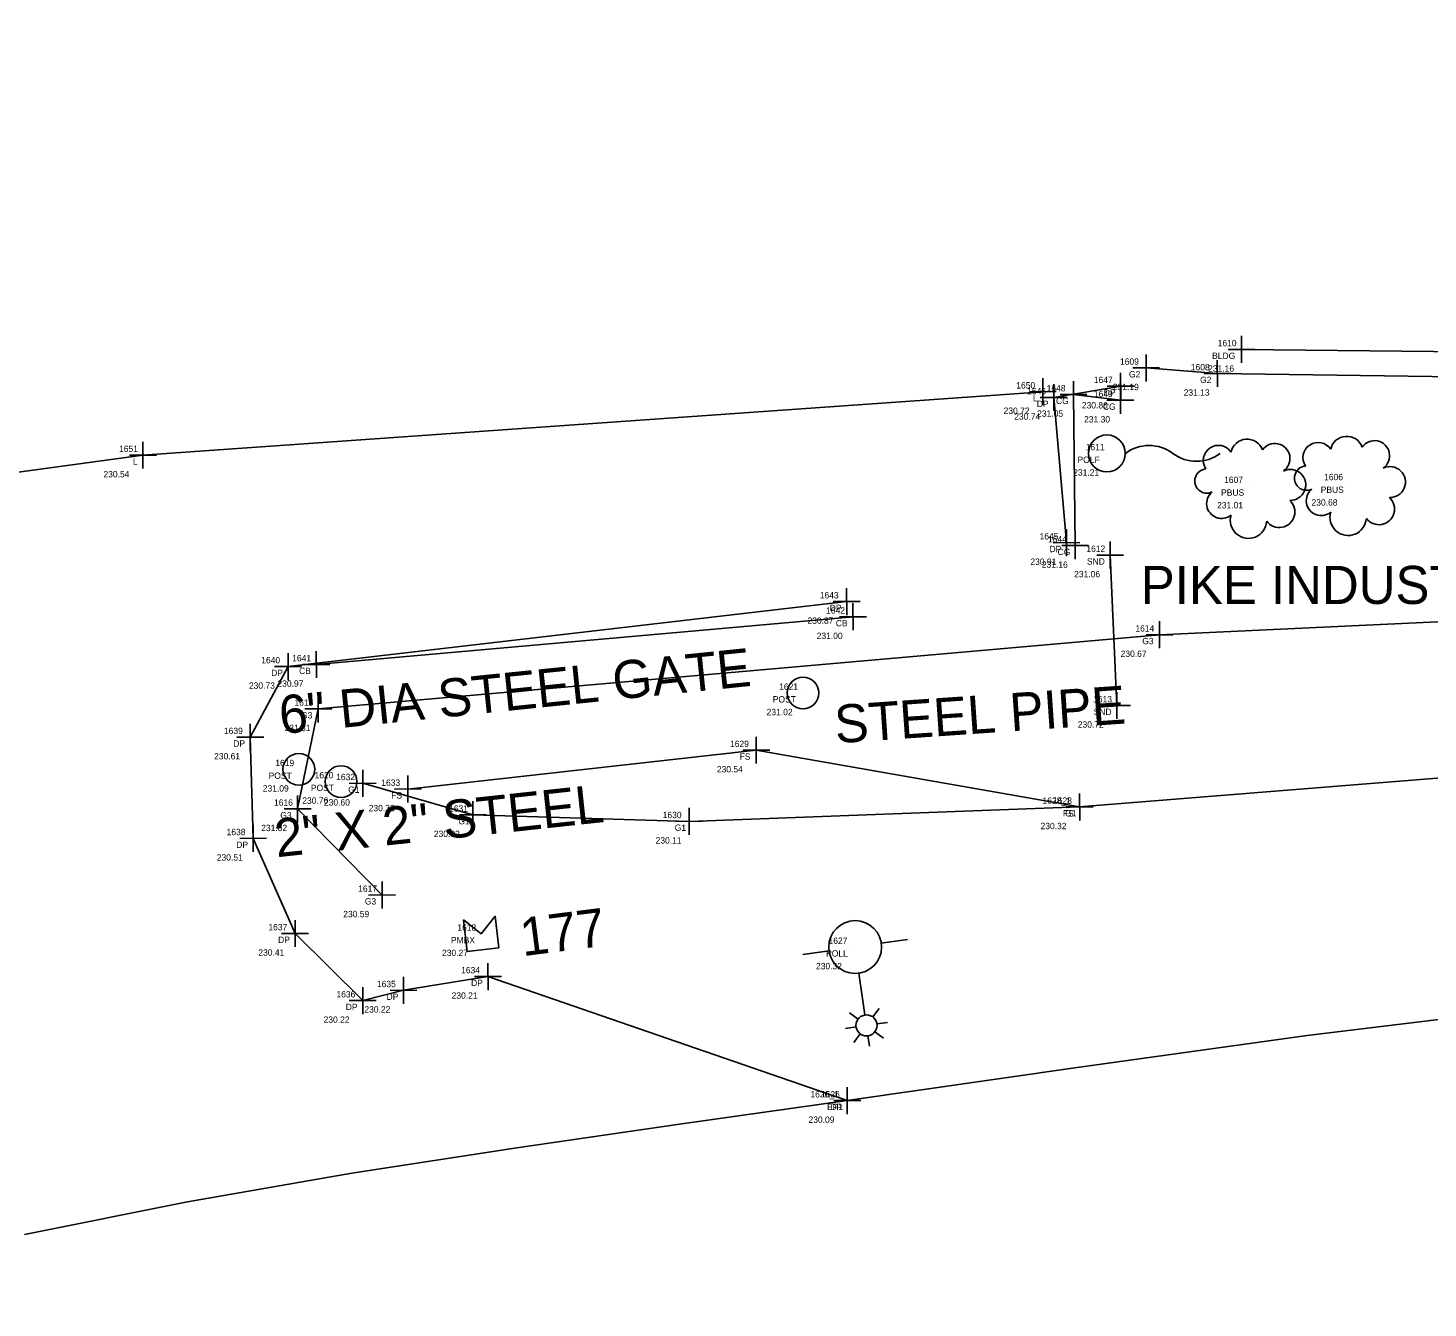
# Model space of a CAD drawing. Extents: x 1155460 to 1157069, y 590691 to 591363.
# Drawn here: x 1155557.4 to 1155623.6, y 591219.6 to 591280.1 of the extents above; entities that cross this region are included whole.
import ezdxf

# ---------------------------------------------------------------- set-up
doc = ezdxf.new("R2010")
doc.units = 0
for name, color, linetype in [('Default', 7, 'Continuous'), ('S_Buildings', 7, 'Continuous'), ('S_Curb_Type_1', 7, 'Continuous'), ('S_Curb_Type_3', 7, 'Continuous'), ('S_Fencing_StockadePostPlank', 7, 'Continuous'), ('S_Field_Code', 7, 'Continuous'), ('S_Ground_Elevation', 7, 'Continuous'), ('S_Ground_LevelString', 7, 'Continuous'), ('S_Point_Elevation', 7, 'Continuous'), ('S_Point_Name', 7, 'Continuous'), ('S_Property_FlagPole', 7, 'Continuous'), ('S_Property_Mailbox', 7, 'Continuous'), ('S_Roadway_Drive_Paved', 7, 'Continuous'), ('S_Roadway_Edge_Pavement', 7, 'Continuous'), ('S_Survey_Shot', 7, 'Continuous'), ('S_Text', 7, 'Continuous'), ('S_Traffic_Posts', 7, 'Continuous'), ('S_Traffic_Sign_DoublePost', 7, 'Continuous'), ('S_Trees_Bush', 7, 'Continuous'), ('S_Utilities_Pole_StreetLight', 7, 'Continuous')]:
    doc.layers.add(name, color=color, linetype=linetype)

msp = doc.modelspace()

# ---------------------------------------------------------------- linework, layer by layer
at = {"layer": 'Default'}
for p, q in [((1155608.443, 591260.021), (1155608.443, 591260.021)), ((1155615.243, 591258.471), (1155615.243, 591258.471)), ((1155619.953, 591258.605), (1155619.953, 591258.605)), ((1155594.081, 591248.698), (1155594.081, 591248.698)), ((1155570.251, 591245.089), (1155570.251, 591245.089)), ((1155572.25, 591244.511), (1155572.25, 591244.511)), ((1155578.87, 591237.315), (1155578.87, 591237.315)), ((1155596.546, 591236.689), (1155596.546, 591236.689))]:
    msp.add_line(p, q, dxfattribs=at)
at = {"layer": 'S_Buildings'}
msp.add_lwpolyline([(1155665.229, 591280.129), (1155664.719, 591264.411), (1155614.806, 591264.937)], dxfattribs=at)
at = {"layer": 'S_Curb_Type_1'}
msp.add_lwpolyline([(1155606.945, 591255.665), (1155606.868, 591262.804), (1155609.086, 591262.533)], dxfattribs=at)
at = {"layer": 'S_Curb_Type_3'}
msp.add_lwpolyline([(1155596.445, 591252.301), (1155571.078, 591250.044)], dxfattribs=at)
at = {"layer": 'S_Fencing_StockadePostPlank'}
msp.add_lwpolyline([(1155575.404, 591244.158), (1155591.874, 591245.993), (1155607.156, 591243.31), (1155631.135, 591245.232), (1155662.71, 591249.078), (1155669.531, 591244.336)], dxfattribs=at)
at = {"layer": 'S_Ground_Elevation'}
for points in [[(1155713.472, 591273.726), (1155710.261, 591263.992), (1155677.396, 591264.939), (1155666.254, 591263.241), (1155644.102, 591263.369), (1155613.665, 591263.8), (1155610.303, 591264.062)], [(1155725.001, 591267.74), (1155722.525, 591258.653), (1155705.308, 591255.632), (1155675.425, 591255.158), (1155658.095, 591253.652), (1155610.931, 591251.452), (1155571.17, 591247.944), (1155570.19, 591243.218), (1155574.185, 591239.149)], [(1156064.685, 591169.992), (1156062.279, 591173.686), (1156058.171, 591175.677), (1156048.24, 591175.877), (1156021.632, 591181.666), (1156002.311, 591185.523), (1155967.868, 591192.884), (1155923.002, 591202.115), (1155873.133, 591212.797), (1155827.029, 591221.651), (1155786.006, 591228.636), (1155747.292, 591234.475), (1155721.081, 591237.232), (1155707.607, 591238.37), (1155671.241, 591246.232), (1155669.531, 591244.336), (1155631.135, 591245.232), (1155607.156, 591243.31), (1155588.703, 591242.631), (1155578.48, 591242.94), (1155573.27, 591244.428)]]:
    msp.add_lwpolyline(points, dxfattribs=at)
at = {"layer": 'S_Ground_LevelString'}
msp.add_lwpolyline([(1155605.415, 591262.939), (1155562.88, 591259.939), (1155527.197, 591255.067), (1155526.793, 591255.817)], dxfattribs=at)
at = {"layer": 'S_Property_FlagPole'}
msp.add_circle((1155608.443, 591260.021), 0.873, dxfattribs=at)
for centre, start, end in [((1155610.439, 591258.524), 53.1301, 126.8699), ((1155612.684, 591261.518), 233.1301, 306.8699)]:
    msp.add_arc(centre, 1.871, start, end, dxfattribs=at)
at = {"layer": 'S_Property_Mailbox'}
msp.add_lwpolyline([(1155578.04, 591237.971), (1155578.214, 591236.484), (1155579.701, 591236.658), (1155579.527, 591238.145), (1155578.87, 591237.315)], close=True, dxfattribs=at)
at = {"layer": 'S_Roadway_Drive_Paved'}
for points in [[(1155606.534, 591255.803), (1155605.93, 591262.665), (1155609.097, 591263.196)], [(1155596.173, 591229.43), (1155579.192, 591235.294), (1155575.198, 591234.643), (1155573.271, 591234.157), (1155570.071, 591237.331), (1155568.093, 591241.827), (1155567.952, 591246.609), (1155569.744, 591249.947), (1155596.144, 591253.017)]]:
    msp.add_lwpolyline(points, dxfattribs=at)
at = {"layer": 'S_Roadway_Edge_Pavement'}
msp.add_lwpolyline([(1155628.79, 591233.837), (1155617.91, 591232.509), (1155607.044, 591230.997), (1155596.173, 591229.43), (1155588.36, 591228.326), (1155580.548, 591227.201), (1155572.755, 591225.996), (1155564.994, 591224.651), (1155557.283, 591223.108)], dxfattribs=at)
at = {"layer": 'S_Survey_Shot'}
for p, q in [((1155614.807, 591264.301), (1155614.805, 591265.574)), ((1155610.304, 591263.426), (1155610.302, 591264.699)), ((1155614.17, 591264.936), (1155615.442, 591264.939)), ((1155614.806, 591264.937), (1155614.806, 591264.937)), ((1155609.667, 591264.061), (1155610.939, 591264.064)), ((1155610.303, 591264.062), (1155610.303, 591264.062)), ((1155613.666, 591263.164), (1155613.663, 591264.436)), ((1155605.417, 591262.303), (1155605.414, 591263.576)), ((1155606.87, 591262.168), (1155606.867, 591263.441)), ((1155609.098, 591262.559), (1155609.095, 591263.832)), ((1155613.028, 591263.798), (1155614.301, 591263.801)), ((1155613.665, 591263.8), (1155613.665, 591263.8)), ((1155604.779, 591262.938), (1155606.051, 591262.941)), ((1155605.415, 591262.939), (1155605.415, 591262.939)), ((1155605.932, 591262.029), (1155605.929, 591263.301)), ((1155606.232, 591262.803), (1155607.504, 591262.806)), ((1155606.868, 591262.804), (1155606.868, 591262.804)), ((1155608.46, 591263.194), (1155609.733, 591263.197)), ((1155609.087, 591261.897), (1155609.084, 591263.169)), ((1155609.097, 591263.196), (1155609.097, 591263.196)), ((1155605.294, 591262.664), (1155606.567, 591262.667)), ((1155605.93, 591262.665), (1155605.93, 591262.665)), ((1155608.449, 591262.532), (1155609.722, 591262.534)), ((1155609.086, 591262.533), (1155609.086, 591262.533)), ((1155562.881, 591259.302), (1155562.878, 591260.575)), ((1155562.243, 591259.937), (1155563.516, 591259.94)), ((1155562.88, 591259.939), (1155562.88, 591259.939)), ((1155606.535, 591255.167), (1155606.533, 591256.439)), ((1155606.946, 591255.029), (1155606.944, 591256.301)), ((1155605.898, 591255.802), (1155607.17, 591255.804)), ((1155606.309, 591255.664), (1155607.581, 591255.666)), ((1155606.534, 591255.803), (1155606.534, 591255.803)), ((1155606.945, 591255.665), (1155606.945, 591255.665)), ((1155608.602, 591254.58), (1155608.599, 591255.853)), ((1155607.964, 591255.215), (1155609.237, 591255.218)), ((1155608.601, 591255.217), (1155608.601, 591255.217)), ((1155596.145, 591252.381), (1155596.143, 591253.653)), ((1155595.508, 591253.016), (1155596.78, 591253.018)), ((1155596.144, 591253.017), (1155596.144, 591253.017)), ((1155596.446, 591251.664), (1155596.443, 591252.937)), ((1155595.808, 591252.299), (1155597.081, 591252.302)), ((1155596.445, 591252.301), (1155596.445, 591252.301)), ((1155610.295, 591251.451), (1155611.568, 591251.453)), ((1155610.933, 591250.816), (1155610.93, 591252.088)), ((1155610.931, 591251.452), (1155610.931, 591251.452)), ((1155569.745, 591249.31), (1155569.742, 591250.583)), ((1155571.079, 591249.408), (1155571.076, 591250.68)), ((1155569.107, 591249.945), (1155570.38, 591249.948)), ((1155569.744, 591249.947), (1155569.744, 591249.947)), ((1155570.441, 591250.043), (1155571.714, 591250.045)), ((1155571.078, 591250.044), (1155571.078, 591250.044)), ((1155571.171, 591247.307), (1155571.168, 591248.58)), ((1155608.922, 591247.47), (1155608.919, 591248.742)), ((1155570.534, 591247.942), (1155571.806, 591247.945)), ((1155571.17, 591247.944), (1155571.17, 591247.944)), ((1155608.284, 591248.105), (1155609.557, 591248.107)), ((1155608.921, 591248.106), (1155608.921, 591248.106)), ((1155567.954, 591245.973), (1155567.951, 591247.245)), ((1155567.316, 591246.608), (1155568.589, 591246.61)), ((1155567.952, 591246.609), (1155567.952, 591246.609)), ((1155591.875, 591245.357), (1155591.873, 591246.629)), ((1155591.238, 591245.992), (1155592.51, 591245.994)), ((1155591.874, 591245.993), (1155591.874, 591245.993)), ((1155573.272, 591243.791), (1155573.269, 591245.064)), ((1155572.634, 591244.426), (1155573.907, 591244.429)), ((1155573.27, 591244.428), (1155573.27, 591244.428)), ((1155575.405, 591243.522), (1155575.402, 591244.794)), ((1155570.192, 591242.581), (1155570.189, 591243.854)), ((1155574.767, 591244.157), (1155576.04, 591244.16)), ((1155575.404, 591244.158), (1155575.404, 591244.158)), ((1155578.482, 591242.304), (1155578.479, 591243.577)), ((1155607.158, 591242.674), (1155607.155, 591243.946)), ((1155607.158, 591242.674), (1155607.155, 591243.946)), ((1155569.554, 591243.216), (1155570.826, 591243.219)), ((1155570.19, 591243.218), (1155570.19, 591243.218)), ((1155577.844, 591242.939), (1155579.117, 591242.942)), ((1155578.48, 591242.94), (1155578.48, 591242.94)), ((1155588.705, 591241.995), (1155588.702, 591243.268)), ((1155606.52, 591243.309), (1155607.793, 591243.311)), ((1155606.52, 591243.309), (1155607.793, 591243.311)), ((1155607.156, 591243.31), (1155607.156, 591243.31)), ((1155607.156, 591243.31), (1155607.156, 591243.31)), ((1155568.095, 591241.191), (1155568.092, 591242.464)), ((1155588.067, 591242.63), (1155589.339, 591242.633)), ((1155588.703, 591242.631), (1155588.703, 591242.631)), ((1155567.457, 591241.826), (1155568.73, 591241.829)), ((1155568.093, 591241.827), (1155568.093, 591241.827)), ((1155574.187, 591238.512), (1155574.184, 591239.785)), ((1155573.549, 591239.147), (1155574.821, 591239.15)), ((1155574.185, 591239.149), (1155574.185, 591239.149)), ((1155570.072, 591236.694), (1155570.07, 591237.967)), ((1155569.435, 591237.329), (1155570.707, 591237.332)), ((1155570.071, 591237.331), (1155570.071, 591237.331)), ((1155579.194, 591234.658), (1155579.191, 591235.93)), ((1155575.199, 591234.007), (1155575.197, 591235.279)), ((1155578.556, 591235.292), (1155579.829, 591235.295)), ((1155579.192, 591235.294), (1155579.192, 591235.294)), ((1155573.272, 591233.52), (1155573.27, 591234.793)), ((1155574.562, 591234.642), (1155575.834, 591234.644)), ((1155575.198, 591234.643), (1155575.198, 591234.643)), ((1155572.635, 591234.155), (1155573.907, 591234.158)), ((1155573.271, 591234.157), (1155573.271, 591234.157)), ((1155596.174, 591228.794), (1155596.171, 591230.067)), ((1155596.174, 591228.794), (1155596.171, 591230.067)), ((1155595.536, 591229.429), (1155596.809, 591229.432)), ((1155595.536, 591229.429), (1155596.809, 591229.432)), ((1155596.173, 591229.43), (1155596.173, 591229.43)), ((1155596.173, 591229.43), (1155596.173, 591229.43))]:
    msp.add_line(p, q, dxfattribs=at)
at = {"layer": 'S_Traffic_Posts'}
for centre in [(1155594.081, 591248.698), (1155570.251, 591245.089), (1155572.25, 591244.511)]:
    msp.add_circle(centre, 0.749, dxfattribs=at)
at = {"layer": 'S_Traffic_Sign_DoublePost'}
msp.add_lwpolyline([(1155608.601, 591255.217), (1155608.921, 591248.106)], dxfattribs=at)
at = {"layer": 'S_Trees_Bush'}
for centre, radius, start, end in [((1155619.78, 591260.056), 0.774, 19.72769, 168.00323), ((1155613.717, 591259.687), 0.716, 33.64054, 213.59091), ((1155615.07, 591259.922), 0.774, 19.72769, 168.00323), ((1155616.385, 591259.777), 0.714, 304.7168, 145.28321), ((1155618.427, 591259.821), 0.716, 33.64054, 213.59091), ((1155621.095, 591259.911), 0.714, 304.7168, 145.28321), ((1155617.883, 591258.853), 0.575, 95.18751, 295.46148), ((1155621.823, 591258.667), 0.731, 268.12197, 116.01721), ((1155613.173, 591258.718), 0.575, 95.18751, 295.46148), ((1155617.112, 591258.533), 0.731, 268.12197, 116.01721), ((1155613.865, 591257.653), 0.705, 129.15555, 309.41051), ((1155618.575, 591257.787), 0.705, 129.15555, 309.41051), ((1155616.588, 591257.257), 0.74, 216.98087, 47.49649), ((1155621.299, 591257.391), 0.74, 216.98087, 47.49649), ((1155615.138, 591256.867), 0.861, 163.74266, 356.27601), ((1155619.849, 591257.001), 0.861, 163.74266, 356.27601)]:
    msp.add_arc(centre, radius, start, end, dxfattribs=at)
at = {"layer": 'S_Utilities_Pole_StreetLight'}
for p, q in [((1155597.78, 591236.867), (1155599.015, 591237.046)), ((1155595.311, 591236.51), (1155594.076, 591236.331)), ((1155596.724, 591235.454), (1155597.01, 591233.479)), ((1155597.381, 591233.384), (1155597.679, 591233.784)), ((1155596.682, 591233.283), (1155596.282, 591233.582)), ((1155597.576, 591233.056), (1155598.07, 591233.128)), ((1155596.588, 591232.913), (1155596.094, 591232.842)), ((1155596.783, 591232.585), (1155596.485, 591232.185)), ((1155597.153, 591232.491), (1155597.225, 591231.997)), ((1155597.482, 591232.686), (1155597.881, 591232.387))]:
    msp.add_line(p, q, dxfattribs=at)
for centre, radius in [((1155596.546, 591236.689), 1.248), ((1155597.082, 591232.985), 0.499)]:
    msp.add_circle(centre, radius, dxfattribs=at)

# ---------------------------------------------------------------- texts
at = {"layer": 'S_Field_Code'}
for s, p in [('BLDG', (1155613.419, 591264.487)), ('G2', (1155609.488, 591263.612)), ('G2', (1155612.85, 591263.35)), ('L', (1155604.943, 591262.489)), ('DP', (1155608.296, 591262.746)), ('DP', (1155605.13, 591262.215)), ('CG', (1155606.039, 591262.354)), ('CG', (1155608.256, 591262.083)), ('L', (1155562.407, 591259.489)), ('POLF', (1155607.056, 591259.571)), ('PBUS', (1155613.842, 591258.021)), ('PBUS', (1155618.552, 591258.155)), ('DP', (1155605.733, 591255.353)), ('CG', (1155606.116, 591255.215)), ('SND', (1155607.5, 591254.767)), ('DP', (1155595.343, 591252.567)), ('CB', (1155595.63, 591251.851)), ('G3', (1155610.116, 591251.002)), ('DP', (1155568.943, 591249.497)), ('CB', (1155570.263, 591249.594)), ('POST', (1155592.652, 591248.248)), ('G3', (1155570.355, 591247.494)), ('SND', (1155607.82, 591247.656)), ('DP', (1155567.152, 591246.159)), ('FS', (1155591.088, 591245.543)), ('POST', (1155568.822, 591244.639)), ('POST', (1155570.821, 591244.061)), ('G1', (1155572.585, 591243.978)), ('FS', (1155574.617, 591243.708)), ('G3', (1155569.375, 591242.768)), ('FS', (1155606.37, 591242.86)), ('G1', (1155606.472, 591242.86)), ('G1', (1155577.795, 591242.49)), ('G1', (1155588.018, 591242.181)), ('DP', (1155567.293, 591241.377)), ('G3', (1155573.37, 591238.699)), ('DP', (1155569.27, 591236.881)), ('PMBX', (1155577.441, 591236.865)), ('POLL', (1155595.173, 591236.239)), ('DP', (1155578.392, 591234.844)), ('DP', (1155574.397, 591234.193)), ('DP', (1155572.47, 591233.707)), ('EP1', (1155595.216, 591228.98)), ('DP', (1155595.372, 591228.98))]:
    msp.add_text(s, height=0.3, dxfattribs=at).set_placement(p)
at = {"layer": 'S_Point_Elevation'}
for s, p in [('231.16', (1155613.228, 591263.887)), ('231.19', (1155608.725, 591263.012)), ('231.13', (1155612.073, 591262.75)), ('230.72', (1155603.563, 591261.889)), ('231.05', (1155605.149, 591261.754)), ('230.86', (1155607.261, 591262.146)), ('230.74', (1155604.065, 591261.615)), ('231.30', (1155607.366, 591261.483)), ('230.54', (1155561.016, 591258.889)), ('231.21', (1155606.851, 591258.971)), ('231.01', (1155613.653, 591257.421)), ('230.68', (1155618.117, 591257.555)), ('230.91', (1155604.829, 591254.753)), ('231.16', (1155605.367, 591254.615)), ('231.06', (1155606.895, 591254.167)), ('230.87', (1155594.292, 591251.967)), ('231.00', (1155594.728, 591251.251)), ('230.67', (1155609.094, 591250.402)), ('230.73', (1155567.892, 591248.897)), ('230.97', (1155569.24, 591248.994)), ('231.02', (1155592.362, 591247.648)), ('231.31', (1155569.578, 591246.894)), ('230.72', (1155607.069, 591247.056)), ('230.61', (1155566.247, 591245.559)), ('230.54', (1155590.01, 591244.943)), ('231.09', (1155568.546, 591244.039)), ('230.76', (1155570.413, 591243.461)), ('230.60', (1155571.438, 591243.378)), ('230.33', (1155573.554, 591243.108)), ('231.02', (1155568.471, 591242.168)), ('230.02', (1155576.633, 591241.89)), ('230.32', (1155605.307, 591242.26)), ('230.32', (1155605.307, 591242.26)), ('230.11', (1155587.114, 591241.581)), ('230.51', (1155566.374, 591240.777)), ('230.59', (1155572.35, 591238.099)), ('230.41', (1155568.337, 591236.281)), ('230.27', (1155577.018, 591236.265)), ('230.32', (1155594.696, 591235.639)), ('230.21', (1155577.473, 591234.244)), ('230.22', (1155573.349, 591233.593)), ('230.22', (1155571.421, 591233.107)), ('230.09', (1155594.34, 591228.38)), ('230.09', (1155594.34, 591228.38))]:
    msp.add_text(s, height=0.3, dxfattribs=at).set_placement(p)
at = {"layer": 'S_Point_Name'}
for s, p in [('1610', (1155613.682, 591265.087)), ('1609', (1155609.063, 591264.212)), ('1608', (1155612.411, 591263.95)), ('1650', (1155604.161, 591263.089)), ('1647', (1155607.824, 591263.346)), ('1646', (1155604.674, 591262.815)), ('1648', (1155605.598, 591262.954)), ('1649', (1155607.829, 591262.683)), ('1651', (1155561.753, 591260.089)), ('1611', (1155607.446, 591260.171)), ('1607', (1155613.986, 591258.621)), ('1606', (1155618.713, 591258.755)), ('1645', (1155605.263, 591255.953)), ('1644', (1155605.66, 591255.815)), ('1612', (1155607.474, 591255.367)), ('1643', (1155594.873, 591253.167)), ('1642', (1155595.174, 591252.451)), ('1614', (1155609.791, 591251.602)), ('1640', (1155568.475, 591250.097)), ('1641', (1155569.937, 591250.194)), ('1621', (1155592.955, 591248.848)), ('1615', (1155570.043, 591248.094)), ('1613', (1155607.794, 591248.256)), ('1639', (1155566.71, 591246.759)), ('1629', (1155590.632, 591246.143)), ('1619', (1155569.139, 591245.239)), ('1620', (1155570.996, 591244.661)), ('1632', (1155572.014, 591244.578)), ('1633', (1155574.147, 591244.308)), ('1616', (1155569.078, 591243.368)), ('1628_1', (1155605.402, 591243.46)), ('1628', (1155605.9, 591243.46)), ('1631', (1155577.354, 591243.09)), ('1630', (1155587.449, 591242.781)), ('1638', (1155566.837, 591241.977)), ('1617', (1155573.056, 591239.299)), ('1637', (1155568.812, 591237.481)), ('1618', (1155577.744, 591237.465)), ('1627', (1155595.287, 591236.839)), ('1634', (1155577.922, 591235.444)), ('1635', (1155573.941, 591234.793)), ('1636', (1155572.029, 591234.307)), ('1626_1', (1155594.432, 591229.58)), ('1626', (1155594.93, 591229.58))]:
    msp.add_text(s, height=0.3, dxfattribs=at).set_placement(p)
at = {"layer": 'S_Text'}
msp.add_text('PIKE INDUSTRIES PLANT 819', height=1.8, dxfattribs=at).set_placement((1155610.048, 591252.905))
for s, rotation, p in [('6" DIA STEEL GATE', 5.85925, (1155569.413, 591246.752)), ('STEEL PIPE', 3.90888, (1155595.634, 591246.319)), ('2" X 2" STEEL', 6.15002, (1155569.204, 591240.93)), ('177', 7.26372, (1155580.833, 591236.254))]:
    msp.add_text(s, height=1.8, rotation=rotation, dxfattribs=at).set_placement(p)

doc.saveas('drawing.dxf')
